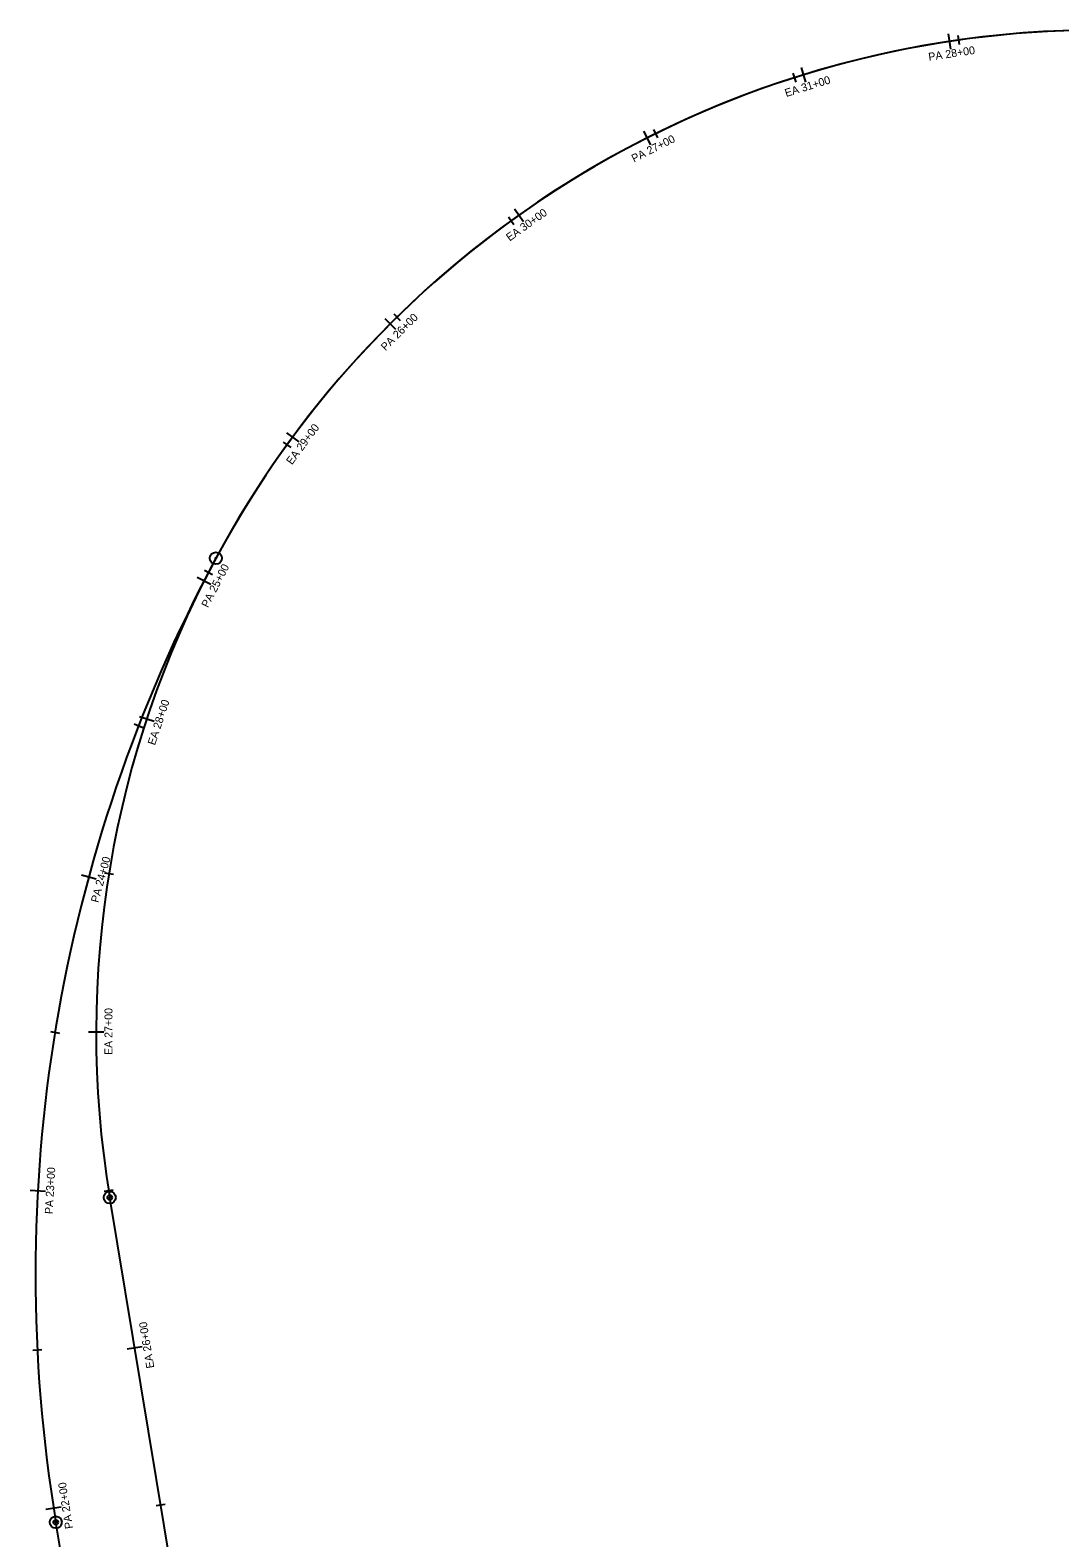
# Model space of a CAD drawing. Extents: x 950864 to 953360, y 1126381 to 1128045.
# Drawn here: x 951961.8 to 952285.2, y 1127568.8 to 1128042.2 of the extents above; entities that cross this region are included whole.
import ezdxf

# ---------------------------------------------------------------- set-up
doc = ezdxf.new("R2010")
doc.units = 0
doc.layers.add('Existing', color=7, linetype='Continuous')
doc.layers.add('Proposed', color=7, linetype='Continuous')

msp = doc.modelspace()

# ---------------------------------------------------------------- linework, layer by layer
at = {"layer": 'Existing'}
msp.add_line((952101.78, 1126982.28), (951986.82, 1127675.69), dxfattribs=at)
for points in [[(952253.17, 1128040.52), (952253.58, 1128037.67)], [(952203.92, 1128030.48), (952205.34, 1128025.9)], [(952157.59, 1128011.01), (952158.86, 1128008.42)], [(952113.94, 1127986.09), (952116.71, 1127982.18)], [(952076, 1127953.13), (952078.02, 1127951.07)], [(952042.3, 1127915.83), (952046.16, 1127912.98)], [(952016.55, 1127872.67), (952019.11, 1127871.35)], [(951996.18, 1127826.72), (952000.74, 1127825.22)], [(951985.19, 1127777.68), (951988.03, 1127777.22)], [(951980.18, 1127727.67), (951984.98, 1127727.66)], [(951985.05, 1127677.64), (951987.89, 1127678.09)], [(951992.27, 1127628.15), (951997.01, 1127628.93)], [(952001.4, 1127578.98), (952004.24, 1127579.45)]]:
    msp.add_lwpolyline(points, dxfattribs=at)
for radius in [1.88, 0.747, 0.156]:
    msp.add_circle((951986.82, 1127675.69), radius, dxfattribs=at)
msp.add_arc((952297.58, 1127727.21), 315, 39.5561, 189.4135, dxfattribs=at)
at = {"layer": 'Proposed'}
msp.add_line((952074.92, 1126940.23), (951969.89, 1127573.74), dxfattribs=at)
for points in [[(952250.08, 1128041.04), (952250.8, 1128036.29)], [(952201.37, 1128028.67), (952202.24, 1128025.93)], [(952154.49, 1128010.53), (952156.66, 1128006.25)], [(952112.07, 1127983.58), (952113.76, 1127981.24)], [(952073.2, 1127951.71), (952076.6, 1127948.32)], [(952041.32, 1127912.86), (952043.65, 1127911.17)], [(952014.32, 1127870.49), (952018.58, 1127868.28)], [(951994.54, 1127824.36), (951997.23, 1127823.31)], [(951977.91, 1127777.01), (951982.54, 1127775.75)], [(951968.21, 1127727.77), (951971.05, 1127727.3)], [(951961.83, 1127677.98), (951966.63, 1127677.72)], [(951962.64, 1127627.8), (951965.52, 1127627.95)], [(951966.81, 1127577.79), (951971.55, 1127578.53)]]:
    msp.add_lwpolyline(points, dxfattribs=at)
for centre, radius in [((952020.15, 1127876.41), 1.89), ((952020.15, 1127876.41), 0.154), ((951969.89, 1127573.74), 1.88), ((951969.89, 1127573.74), 0.747), ((951969.89, 1127573.74), 0.156)]:
    msp.add_circle(centre, radius, dxfattribs=at)
for centre, radius, start, end in [((952297.58, 1127727.21), 315, 39.5561, 151.7306), ((952438.5, 1127651.43), 475, 151.7306, 189.4135)]:
    msp.add_arc(centre, radius, start, end, dxfattribs=at)

# ---------------------------------------------------------------- texts
at = {"layer": 'Existing'}
for s, rotation, p in [('EA 31+00', 17.1616, (952199.26, 1128021.21)), ('EA 30+00', 35.3507, (952112.4, 1127975.82)), ('EA 29+00', 53.5398, (952044.03, 1127905.57)), ('EA 28+00', 71.729, (952001.02, 1127817.51)), ('EA 27+00', 89.9181, (951987.66, 1127720.43)), ('EA 26+00', 99.4135, (952000.84, 1127622.26))]:
    msp.add_text(s, height=2.496, rotation=rotation, dxfattribs=at).set_placement(p)
at = {"layer": 'Proposed'}
for s, rotation, p in [('PA 28+00', 8.6061, (952244.09, 1128032.56)), ('PA 27+00', 26.7953, (952151.45, 1128000.61)), ('PA 26+00', 44.9844, (952073.43, 1127941.35)), ('PA 25+00', 62.6875, (952017.67, 1127860.67)), ('PA 24+00', 74.7498, (951983.24, 1127768.1)), ('PA 23+00', 86.812, (951968.91, 1127670.42)), ('PA 22+00', 98.8743, (951975.32, 1127571.84))]:
    msp.add_text(s, height=2.496, rotation=rotation, dxfattribs=at).set_placement(p)

doc.saveas('drawing.dxf')
